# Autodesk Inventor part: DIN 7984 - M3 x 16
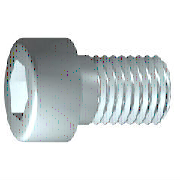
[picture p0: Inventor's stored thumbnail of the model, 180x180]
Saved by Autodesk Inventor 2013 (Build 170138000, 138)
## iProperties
IsCustomPart: 0
Created: 2012-02
Part Number: DIN 7984 - M3 x 16
Material: Steel, Mild
Description: Cylinder Head Cap Screw
Document SubType Name: Modeling
Standard: DIN 7984
Designer: rYan
Standard Revision: 1985
Standards Organization: DIN
Language: en-US
Size Designation: M3 x 16
Categories: <MemberInstance><Categories><Category DisplayName="Fasteners" InternalName="e4da775c-781d-43d5-af7c-5136215cf5a6" Mnemonic="FSTN"><Category DisplayName="Bolts"
Density: 1 g/cm^3
Author: rYan
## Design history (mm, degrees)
sketch "Sketch1"
  geometry: L1 (0.167, 0)-(16, 0); L2 (16, 0)-(16, 1.5); L3 (16, 1.5)-(1.5, 1.5); L4 (1.5, 1.5)-(1.193, 1.5); L5 (1.193, 1.5)-(0, 1.5); L6 (0, 1.5)-(0, 2.75); L7 (0, 2.75)-(-2, 2.75); L8 (-2, 2.75)-(-2, 1.155); L9 (-2, 1.155)-(-0.5, 1.155); L10 (-0.5, 1.155)-(0.167, 0); L11 (-5.6, 0)-(19.6, 0) reference; L12 (0, -0.55)-(0, 3.3) reference; L13 (1.5, 1.5)-(0, 1.5)
  constraints: 22 end point, 6 parallel, 2 collinear, 2 perpendicular, 1 horizontal, 1 point on line
  dimensions: "d1" = 14.5 distance from line of L3.end L2 (= GEL); "d2" = 0.30683 distance of L4.end L3.end (computed from GAL); "d3" = 2 distance between parallel lines of L8 L6 (= KOH); "d4" = 1.5 distance of L8.end L9.end (= INTI); "d5" = 60 deg angle of L10 L1; "d6" = 3 diameter of L3 L1 (= GD); "d7" = 3 diameter of L5 L1 (= BDM); "d8" = 2.3094 diameter of L9 L1 (= 1.1547 x SW); "d9" = 5.5 diameter of L7 L1 (= KOD); "d26" = 16 distance between parallel lines of L12 L2 (= NLG)
revolve "Body" sketch "Sketch1" stored, may be unused: angle "d10" = 90 deg
sketch "Sketch2"
  geometry: L1 (0, -3.85)-(0, 3.85) reference; L2 (-3.85, 0)-(3.85, 0) reference; L3 (1.155, 0)-(0.577, -1); L4 (0.577, -1)-(-0.577, -1); L5 (-0.577, -1)-(-1.155, 0); L6 (-1.155, 0)-(-0.577, 1); L7 (-0.577, 1)-(0.577, 1); L8 (0.577, 1)-(1.155, 0); 2 further points
  constraints: 12 end point, 1 coincident, 1 horizontal alignment, 1 point on line, 12 other
extrude "Slot" join sketch "Sketch2" stored distance "d11" = 10; taper "d12" = 0 deg
workplane "Work Plane1"
fillet "Fillet2" dims "d30" = 0.1 (= R)
body "Solid1"
fillet "Fillet1" dims "d17" = 0.3 (= RR)
feature "Thread" dims "d13" = 14.5 (= GEL), "d14" = 0
chamfer "Chamfer1" distance "d15" = 0.30673 (= -0.5 x SPD + 0.5 x GD); stored, may be unused: second distance "d16" = 0.30673 (= GUL), angle "d27" = 45 deg
other parameters: "GD" = 3 (= NND) [user parameter; used in 2 equation terms], "NLG" = 16 [user parameter; used in 1 equation term], "GEL" = 14.5 [user parameter; used in 2 equation terms], "KOD" = 5.5 [user parameter; used in 1 equation term], "KOH" = 2 [user parameter; used in 1 equation term], "INTI" = 1.5 [user parameter; used in 1 equation term], "GAL" = 0.30673 (= 0.61345 x PTC) [user parameter; used in 1 equation term], "GUL" = 0.30673 (= 0.61345 x PTC) [user parameter; used in 1 equation term], "BDM" = 3 (= NND) [user parameter; used in 1 equation term], "SW" = 2 [user parameter; used in 2 equation terms], "RR" = 0.3 [user parameter; used in 1 equation term], "SPD" = 2.38655 (= NND - 1.2269 x PTC) [user parameter; used in 1 equation term], "d19" = 0, "d28" = 0, "d29" = 0, "R" = 0.1 [user parameter; used in 1 equation term], "TOA" = 30 deg [user parameter], "GD1" = 2.38655 (= THREADDIA - 1.2269 x PTC) [user parameter], "THREADDIA" = 3 [user parameter; used in 1 equation term], "FAWI" = 45 deg [user parameter], "ANG" = 120 deg [user parameter], "PTC" = 0.5 [user parameter; used in 5 equation terms], "NND" = 3 [user parameter; used in 3 equation terms], "E0" = 2.31 (= 1.155 x SW) [user parameter]
